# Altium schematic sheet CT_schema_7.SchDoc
size 371 x 245 mm
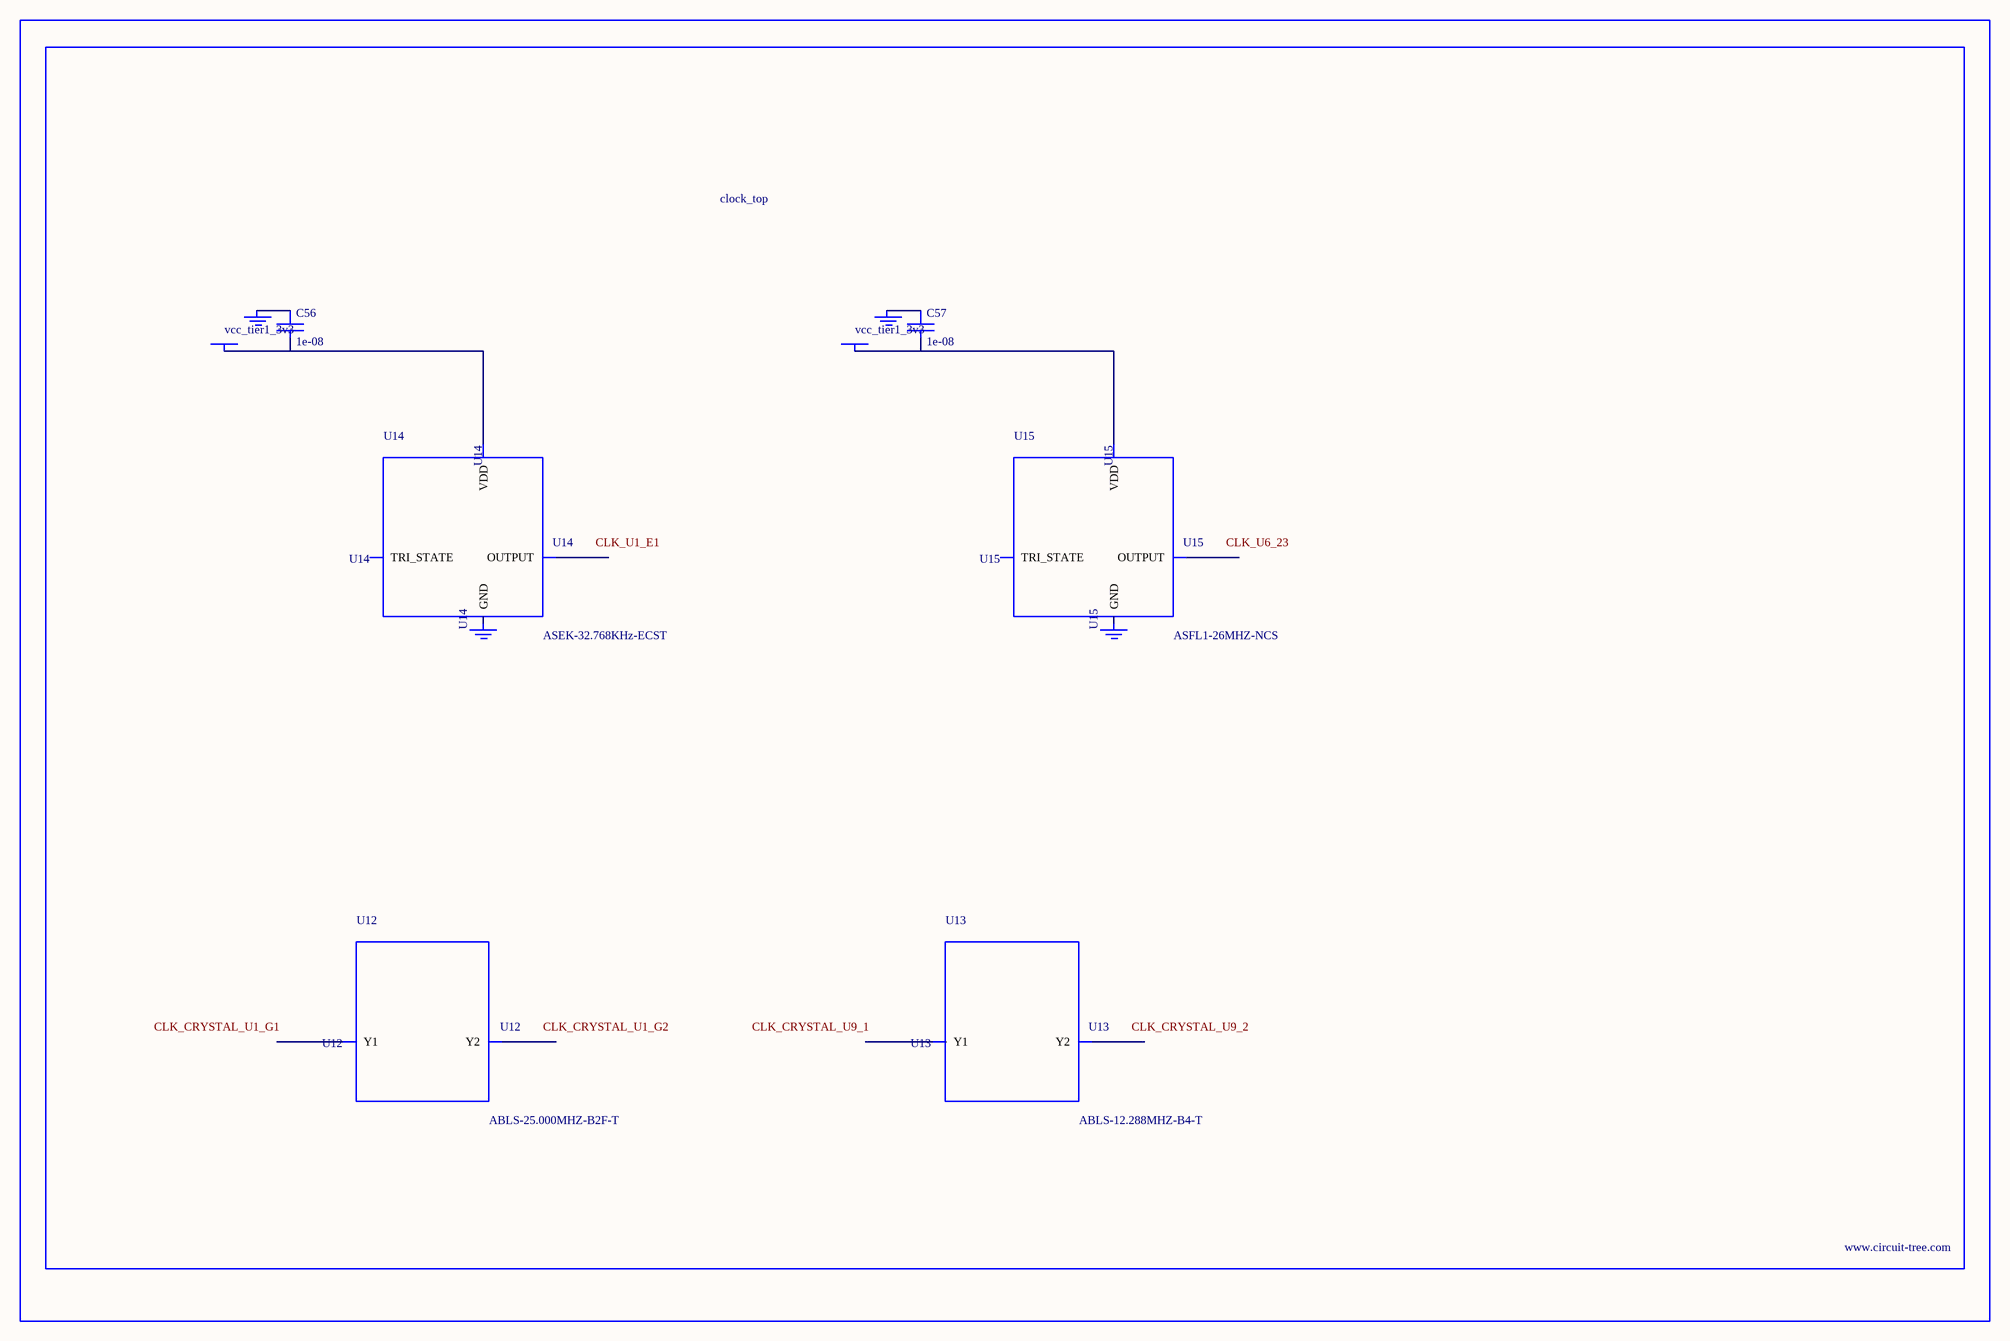
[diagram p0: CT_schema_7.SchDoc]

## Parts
BORDER6  (no value)
C56  1e-08  [C0402]
C57  1e-08  [C0402]
GND_INSTANCE_6_0  (no value)
GND_INSTANCE_6_1  (no value)
GND_INSTANCE_6_2  (no value)
GND_INSTANCE_6_3  (no value)
POWER_INSTANCE_6_0  vcc_tier1_3v3
POWER_INSTANCE_6_1  vcc_tier1_3v3
U12  ABLS-25.000MHZ-B2F-T  [ABLS-25.000MHZ-B2F-T]
U13  ABLS-12.288MHZ-B4-T  [ABLS-12.288MHZ-B4-T]
U14  ASEK-32.768KHz-ECST  [ASEK]
U15  ASFL1-26MHZ-NCS  [ASFL1]

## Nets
NetC56_1: C56.1 GND_INSTANCE_6_0.0(GND)
NetC56_2: C56.2 POWER_INSTANCE_6_0.0(PWR) U14.4(VDD)
NetC57_1: C57.1 GND_INSTANCE_6_2.0(GND)
NetC57_2: C57.2 POWER_INSTANCE_6_1.0(PWR) U15.4(VDD)

Not connected (* = marked no-connect by the designer): GND_INSTANCE_6_1 0(GND); GND_INSTANCE_6_3 0(GND); U12 1(Y1) 2(Y2); U13 1(Y1) 2(Y2); U14 1(TRI_STATE) 2(GND) 3(OUTPUT); U15 1(TRI_STATE) 2(GND) 3(OUTPUT)

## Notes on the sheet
- Labels drawn without touching a wire or pin: CLK_CRYSTAL_U1_G1, CLK_CRYSTAL_U1_G2, CLK_CRYSTAL_U9_1, CLK_CRYSTAL_U9_2, CLK_U1_E1, CLK_U6_23

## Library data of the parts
BORDER6 = BORDER_PAGE6
C56 C57 = C0402C103K3RAC
GND_INSTANCE_6_0-GND_INSTANCE_6_3 = GND
POWER_INSTANCE_6_0 POWER_INSTANCE_6_1 = PWR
